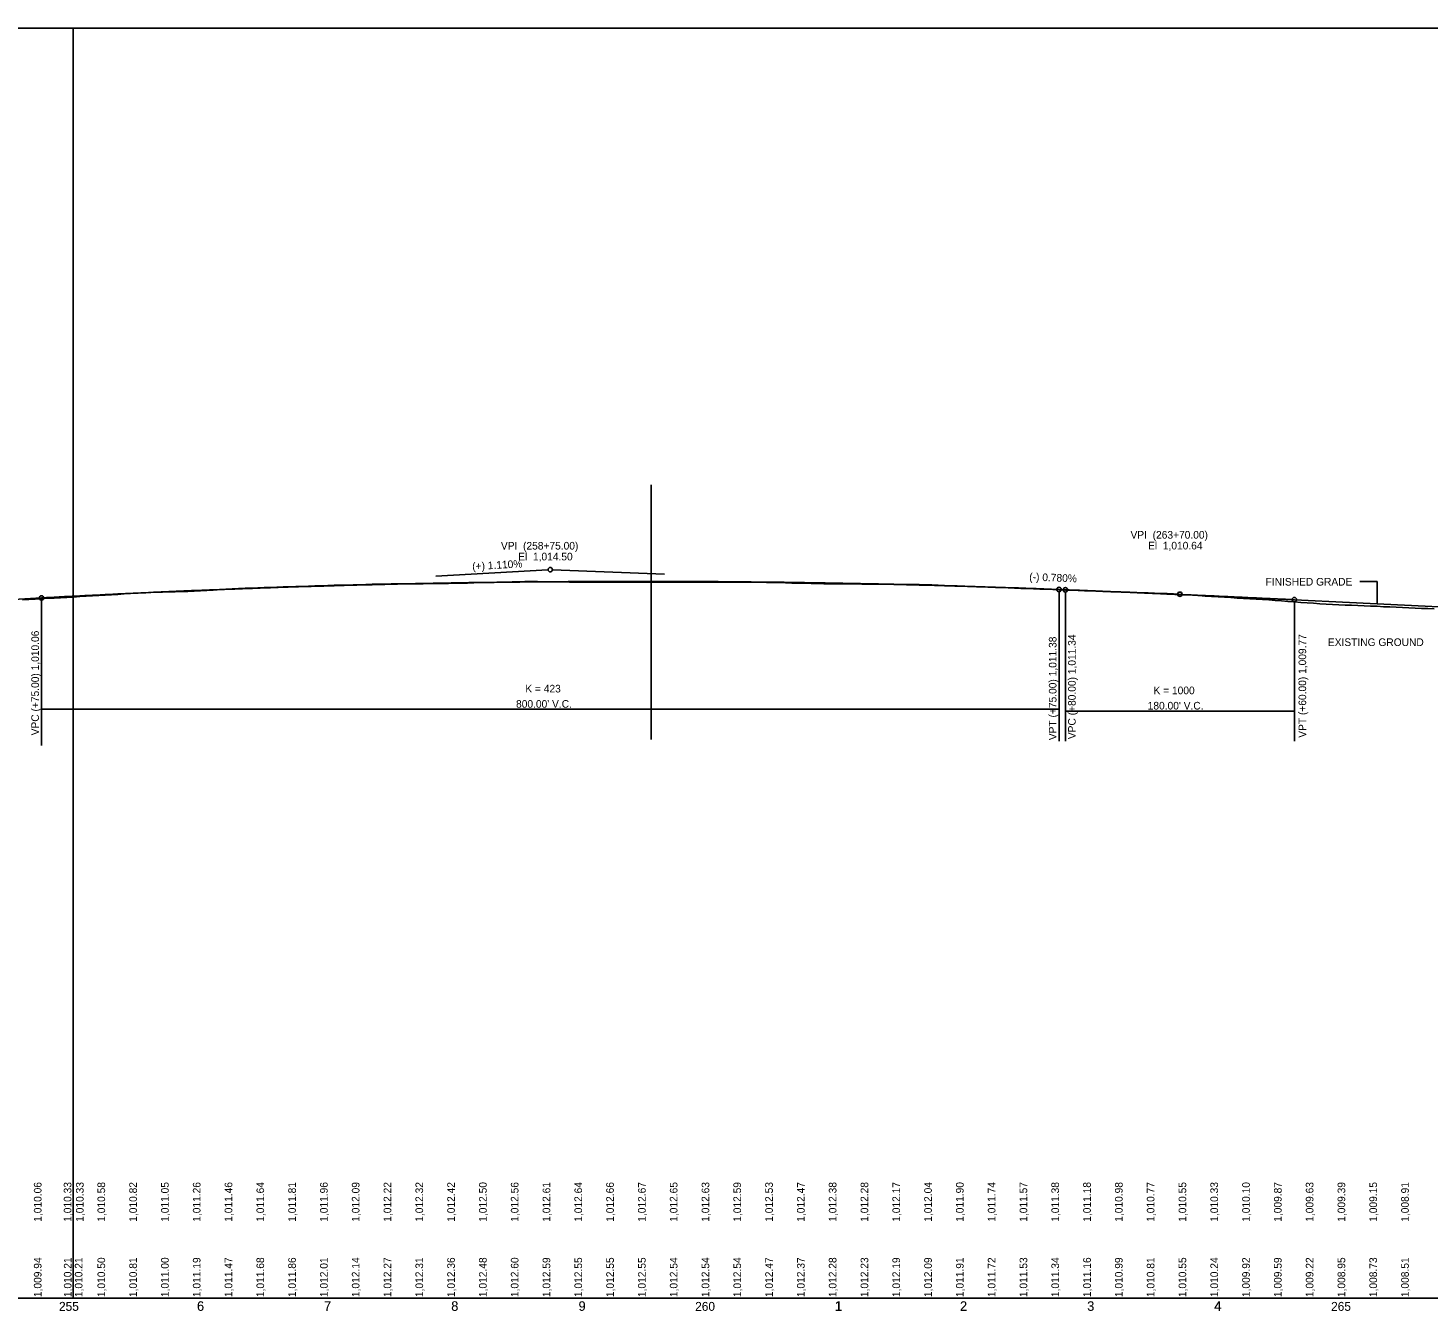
# Model space of a CAD drawing. Extents: x 1608361 to 16979326, y 1092015 to 12565288.
# Drawn here: x 16974450 to 16975551, y 12564278 to 12565286 of the extents above; entities that cross this region are included whole.
import ezdxf

# ---------------------------------------------------------------- set-up
doc = ezdxf.new("R2010")
doc.units = 0
for name, color, linetype in [('CLS_Median', 7, 'Continuous'), ('Default', 7, 'Continuous'), ('points EP', 7, 'Continuous'), ('RD_DDB_EX_Tx', 7, 'Continuous'), ('RD_EX_Fence_ChLk', 7, 'Continuous'), ('RD_EX_H2O', 7, 'Continuous'), ('RD_EX_RW_Approx', 7, 'Continuous'), ('RD_EX_SU_Water', 7, 'Continuous'), ('RD_EX_UT', 7, 'Continuous'), ('RD_HC_TX_Rel_Sta50', 7, 'Continuous'), ('RD_PD_BCA', 7, 'Continuous'), ('RD_PD_Final_TX', 7, 'Continuous'), ('TEXT2', 7, 'Continuous')]:
    doc.layers.add(name, color=color, linetype=linetype)

msp = doc.modelspace()

# ---------------------------------------------------------------- linework, layer by layer
at = {"layer": 'CLS_Median'}
for p, q in [((16975497.2, 12564851), (16975510.6, 12564851)), ((16975510.6, 12564851), (16975510.6, 12564833.5))]:
    msp.add_line(p, q, dxfattribs=at)
at = {"layer": 'Default'}
for points in [[(16972985.6, 12564287.8), (16974485.6, 12564287.8), (16974485.6, 12565286), (16972985.6, 12565286)], [(16974485.6, 12564287.8), (16975985.6, 12564287.8), (16975985.6, 12565286), (16974485.6, 12565286)]]:
    msp.add_lwpolyline(points, close=True, dxfattribs=at)
at = {"layer": 'RD_EX_Fence_ChLk'}
for p, q in [((16975260.6, 12564725.4), (16975260.6, 12564842.9)), ((16975265.6, 12564725.4), (16975265.6, 12564842.7)), ((16974460.6, 12564722.2), (16974460.6, 12564836.3)), ((16975445.6, 12564725.4), (16975445.6, 12564834.9)), ((16974460.6, 12564750.6), (16975260.6, 12564750.6)), ((16975265.6, 12564749.2), (16975445.6, 12564749.2))]:
    msp.add_line(p, q, dxfattribs=at)
for centre in [(16974460.6, 12564838.1), (16975260.6, 12564844.7), (16975265.6, 12564844.5), (16975445.6, 12564836.7)]:
    msp.add_circle(centre, 1.75, dxfattribs=at)
at = {"layer": 'RD_EX_H2O'}
for points in [[(16974485.6, 12564838.8), (16974490.6, 12564839.1), (16974495.6, 12564839.4), (16974500.6, 12564839.7), (16974505.6, 12564840), (16974510.6, 12564840.3), (16974515.6, 12564840.6), (16974520.6, 12564840.9), (16974525.6, 12564841.2), (16974530.6, 12564841.5), (16974535.6, 12564841.8), (16974540.6, 12564842.2), (16974545.6, 12564842.3), (16974550.6, 12564842.5), (16974555.6, 12564842.6), (16974560.6, 12564842.8), (16974565.6, 12564842.9), (16974570.6, 12564843.1), (16974575.6, 12564843.2), (16974580.6, 12564843.5), (16974585.6, 12564843.7), (16974590.6, 12564844), (16974595.6, 12564844.3), (16974600.6, 12564844.6), (16974605.6, 12564844.9), (16974610.6, 12564845.2), (16974615.6, 12564845.4), (16974620.6, 12564845.7), (16974625.6, 12564845.8), (16974630.6, 12564846), (16974635.6, 12564846.2), (16974640.6, 12564846.4), (16974645.6, 12564846.6), (16974650.6, 12564846.7), (16974655.6, 12564846.9), (16974660.6, 12564847.1), (16974665.6, 12564847.2), (16974670.6, 12564847.4), (16974675.6, 12564847.5), (16974680.6, 12564847.7), (16974685.6, 12564847.8), (16974690.6, 12564848), (16974695.6, 12564848.1), (16974700.6, 12564848.2), (16974705.6, 12564848.4), (16974710.6, 12564848.5), (16974715.6, 12564848.6), (16974720.6, 12564848.8), (16974725.6, 12564848.9), (16974730.6, 12564849), (16974735.6, 12564849.1), (16974740.6, 12564849.2), (16974745.6, 12564849.3), (16974750.6, 12564849.3), (16974755.6, 12564849.3), (16974760.6, 12564849.3), (16974765.6, 12564849.4), (16974770.6, 12564849.4), (16974775.6, 12564849.4), (16974780.6, 12564849.5), (16974785.6, 12564849.6), (16974790.6, 12564849.7), (16974795.6, 12564849.8), (16974800.6, 12564849.9), (16974805.6, 12564850.1), (16974810.6, 12564850.2), (16974815.6, 12564850.3), (16974820.6, 12564850.4), (16974825.6, 12564850.5), (16974830.6, 12564850.7), (16974835.6, 12564850.8), (16974840.6, 12564850.9), (16974845.6, 12564850.9), (16974850.6, 12564850.9), (16974855.6, 12564850.8), (16974860.6, 12564850.8), (16974865.6, 12564850.7), (16974870.6, 12564850.7), (16974875.6, 12564850.6), (16974880.6, 12564850.6), (16974885.6, 12564850.5), (16974890.6, 12564850.5), (16974895.6, 12564850.5), (16974900.6, 12564850.5), (16974905.6, 12564850.5), (16974910.6, 12564850.5), (16974915.6, 12564850.5), (16974920.6, 12564850.5), (16974925.6, 12564850.5), (16974930.6, 12564850.5), (16974935.6, 12564850.5), (16974940.6, 12564850.5), (16974945.6, 12564850.5), (16974950.6, 12564850.5), (16974955.6, 12564850.5), (16974960.6, 12564850.5), (16974965.6, 12564850.5), (16974970.6, 12564850.5), (16974975.6, 12564850.5), (16974980.6, 12564850.5), (16974985.6, 12564850.5)], [(16974985.6, 12564850.5), (16974990.6, 12564850.5), (16974995.6, 12564850.5), (16975000.6, 12564850.5), (16975005.6, 12564850.5), (16975010.6, 12564850.5), (16975015.6, 12564850.5), (16975020.6, 12564850.5), (16975025.6, 12564850.4), (16975030.6, 12564850.3), (16975035.6, 12564850.2), (16975040.6, 12564850.1), (16975045.6, 12564849.9), (16975050.6, 12564849.8), (16975055.6, 12564849.7), (16975060.6, 12564849.6), (16975065.6, 12564849.5), (16975070.6, 12564849.4), (16975075.6, 12564849.3), (16975080.6, 12564849.2), (16975085.6, 12564849.2), (16975090.6, 12564849.1), (16975095.6, 12564849.1), (16975100.6, 12564849.1), (16975105.6, 12564849), (16975110.6, 12564849), (16975115.6, 12564848.9), (16975120.6, 12564848.9), (16975125.6, 12564848.8), (16975130.6, 12564848.8), (16975135.6, 12564848.7), (16975140.6, 12564848.7), (16975145.6, 12564848.6), (16975150.6, 12564848.6), (16975155.6, 12564848.4), (16975160.6, 12564848.3), (16975165.6, 12564848.1), (16975170.6, 12564847.9), (16975175.6, 12564847.7), (16975180.6, 12564847.5), (16975185.6, 12564847.3), (16975190.6, 12564847.1), (16975195.6, 12564846.9), (16975200.6, 12564846.8), (16975205.6, 12564846.6), (16975210.6, 12564846.4), (16975215.6, 12564846.2), (16975220.6, 12564846), (16975225.6, 12564845.8), (16975230.6, 12564845.6), (16975235.6, 12564845.4), (16975240.6, 12564845.3), (16975245.6, 12564845.1), (16975250.6, 12564844.9), (16975255.6, 12564844.7), (16975260.6, 12564844.5), (16975265.6, 12564844.3), (16975270.6, 12564844.1), (16975275.6, 12564844), (16975280.6, 12564843.8), (16975285.6, 12564843.6), (16975290.6, 12564843.4), (16975295.6, 12564843.2), (16975300.6, 12564843.1), (16975305.6, 12564842.9), (16975310.6, 12564842.7), (16975315.6, 12564842.5), (16975320.6, 12564842.4), (16975325.6, 12564842.2), (16975330.6, 12564842), (16975335.6, 12564841.8), (16975340.6, 12564841.6), (16975345.6, 12564841.5), (16975350.6, 12564841.2), (16975355.6, 12564840.9), (16975360.6, 12564840.6), (16975365.6, 12564840.2), (16975370.6, 12564839.9), (16975375.6, 12564839.6), (16975380.6, 12564839.3), (16975385.6, 12564839), (16975390.6, 12564838.7), (16975395.6, 12564838.4), (16975400.6, 12564838), (16975405.6, 12564837.7), (16975410.6, 12564837.4), (16975415.6, 12564837.1), (16975420.6, 12564836.8), (16975425.6, 12564836.5), (16975430.6, 12564836.1), (16975435.6, 12564835.7), (16975440.6, 12564835.3), (16975445.6, 12564835), (16975450.6, 12564834.6), (16975455.6, 12564834.2), (16975460.6, 12564833.9), (16975465.6, 12564833.5), (16975470.6, 12564833.1), (16975475.6, 12564832.9), (16975480.6, 12564832.7), (16975485.6, 12564832.5)], [(16974445.6, 12564836.7), (16974450.6, 12564836.9), (16974455.6, 12564837.2), (16974460.6, 12564837.5), (16974465.6, 12564837.8), (16974470.6, 12564838), (16974475.6, 12564838.3), (16974480.6, 12564838.5), (16974485.6, 12564838.8)], [(16975485.6, 12564832.5), (16975490.6, 12564832.3), (16975495.6, 12564832.1), (16975500.6, 12564831.9), (16975505.6, 12564831.7), (16975510.6, 12564831.5), (16975515.6, 12564831.2), (16975520.6, 12564831), (16975525.6, 12564830.8), (16975530.6, 12564830.6), (16975535.6, 12564830.3), (16975540.6, 12564830.1), (16975545.6, 12564829.9), (16975550.6, 12564829.7), (16975555.6, 12564829.6)]]:
    msp.add_lwpolyline(points, dxfattribs=at)
at = {"layer": 'RD_EX_RW_Approx'}
for p, q in [((16974770.7, 12564855.3), (16974858.8, 12564860.2)), ((16974950.5, 12564856.8), (16974862.3, 12564860.2)), ((16975265.6, 12564844.5), (16975353.8, 12564841)), ((16975445.5, 12564836.7), (16975357.3, 12564840.9))]:
    msp.add_line(p, q, dxfattribs=at)
for centre in [(16974860.6, 12564860.3), (16975355.6, 12564841)]:
    msp.add_circle(centre, 1.75, dxfattribs=at)
at = {"layer": 'RD_EX_UT'}
msp.add_line((16972985.6, 12564287.8), (16978789.9, 12564287.8), dxfattribs=at)
at = {"layer": 'RD_HC_TX_Rel_Sta50'}
for p, q in [((16975260.6, 12564844.7), (16975265.6, 12564844.5)), ((16974390.6, 12564834.2), (16974460.6, 12564838.1)), ((16975445.6, 12564836.7), (16975735.6, 12564822.7))]:
    msp.add_line(p, q, dxfattribs=at)
for points in [[(16974460.6, 12564838.1), (16974476.6, 12564839), (16974492.6, 12564839.8), (16974508.6, 12564840.6), (16974524.6, 12564841.4), (16974540.6, 12564842.1), (16974556.6, 12564842.9), (16974572.6, 12564843.6), (16974588.6, 12564844.2), (16974604.6, 12564844.8), (16974620.6, 12564845.4), (16974636.6, 12564846), (16974652.6, 12564846.6), (16974668.6, 12564847.1), (16974684.6, 12564847.5), (16974700.6, 12564848), (16974716.6, 12564848.4), (16974732.6, 12564848.8), (16974748.6, 12564849.2), (16974764.6, 12564849.5), (16974780.6, 12564849.8), (16974796.6, 12564850.1), (16974812.6, 12564850.3), (16974828.6, 12564850.5), (16974844.6, 12564850.7), (16974860.6, 12564850.8), (16974876.6, 12564850.9), (16974892.6, 12564851), (16974908.6, 12564851.1), (16974924.6, 12564851.1), (16974940.6, 12564851.1), (16974956.6, 12564851.1), (16974972.6, 12564851), (16974988.6, 12564850.9), (16975004.6, 12564850.8), (16975020.6, 12564850.6), (16975036.6, 12564850.5), (16975052.6, 12564850.2), (16975068.6, 12564850), (16975084.6, 12564849.7), (16975100.6, 12564849.4), (16975116.6, 12564849.1), (16975132.6, 12564848.7), (16975148.6, 12564848.3), (16975164.6, 12564847.9), (16975180.6, 12564847.4), (16975196.6, 12564846.9), (16975212.6, 12564846.4), (16975228.6, 12564845.9), (16975244.6, 12564845.3), (16975260.6, 12564844.7)], [(16975265.6, 12564844.5), (16975269.2, 12564844.3), (16975272.8, 12564844.2), (16975276.4, 12564844.1), (16975280, 12564843.9), (16975283.6, 12564843.8), (16975287.2, 12564843.6), (16975290.8, 12564843.5), (16975294.4, 12564843.3), (16975298, 12564843.2), (16975301.6, 12564843), (16975305.2, 12564842.9), (16975308.8, 12564842.8), (16975312.4, 12564842.6), (16975316, 12564842.5), (16975319.6, 12564842.3), (16975323.2, 12564842.2), (16975326.8, 12564842), (16975330.4, 12564841.9), (16975334, 12564841.7), (16975337.6, 12564841.5), (16975341.2, 12564841.4), (16975344.8, 12564841.2), (16975348.4, 12564841.1), (16975352, 12564840.9), (16975355.6, 12564840.8), (16975359.2, 12564840.6), (16975362.8, 12564840.5), (16975366.4, 12564840.3), (16975370, 12564840.1), (16975373.6, 12564840), (16975377.2, 12564839.8), (16975380.8, 12564839.7), (16975384.4, 12564839.5), (16975388, 12564839.3), (16975391.6, 12564839.2), (16975395.2, 12564839), (16975398.8, 12564838.8), (16975402.4, 12564838.7), (16975406, 12564838.5), (16975409.6, 12564838.3), (16975413.2, 12564838.2), (16975416.8, 12564838), (16975420.4, 12564837.8), (16975424, 12564837.7), (16975427.6, 12564837.5), (16975431.2, 12564837.3), (16975434.8, 12564837.2), (16975438.4, 12564837), (16975442, 12564836.8), (16975445.6, 12564836.7)]]:
    msp.add_spline(points, degree=3, dxfattribs=at)
at = {"layer": 'RD_PD_BCA'}
msp.add_line((16974940, 12564726.8), (16974940, 12564926.9), dxfattribs=at)

# ---------------------------------------------------------------- texts
at = {"layer": 'CLS_Median'}
msp.add_text('FINISHED GRADE', height=6, dxfattribs=at).set_placement((16975423, 12564847.8))
at = {"layer": 'points EP'}
for s, rotation, p in [('(+) 1.110%', 3.1767, (16974799.4, 12564859.9)), ('(-) 0.780%', 357.7666, (16975237.1, 12564851.8))]:
    msp.add_text(s, height=6, rotation=rotation, dxfattribs=at).set_placement(p)
at = {"layer": 'RD_DDB_EX_Tx'}
msp.add_text('EXISTING GROUND', height=6, dxfattribs=at).set_placement((16975472, 12564800.3))
at = {"layer": 'RD_EX_Fence_ChLk'}
for s, p in [('VPC (+75.00) 1,010.06', (16974458.6, 12564730.1)), ('VPT (+75.00) 1,011.38', (16975258.6, 12564726.3)), ('VPC (+80.00) 1,011.34', (16975273.7, 12564727.1)), ('VPT (+60.00) 1,009.77', (16975454.9, 12564728.2))]:
    msp.add_text(s, height=6, rotation=90, dxfattribs=at).set_placement(p)
for s, p in [('K = 423', (16974841, 12564763.8)), ('K = 1000', (16975334.9, 12564762.4)), ("800.00' V.C.", (16974833.7, 12564751.8)), ("180.00' V.C.", (16975330.3, 12564750.4))]:
    msp.add_text(s, height=6, dxfattribs=at).set_placement(p)
at = {"layer": 'RD_EX_RW_Approx'}
for s, p in [('VPI  (258+75.00)', (16974821.8, 12564876.1)), ('VPI  (263+70.00)', (16975316.8, 12564884.7)), ('El  1,010.64', (16975330.6, 12564876.2)), ('El  1,014.50', (16974835.4, 12564867.6))]:
    msp.add_text(s, height=6, dxfattribs=at).set_placement(p)
at = {"layer": 'RD_EX_SU_Water'}
for s, p in [('1,010.06', (16974460.6, 12564347.8)), ('1,010.33', (16974484.1, 12564347.8)), ('1,010.33', (16974493.7, 12564347.8)), ('1,010.58', (16974510.6, 12564347.8)), ('1,010.82', (16974535.6, 12564347.8)), ('1,011.05', (16974560.6, 12564347.8)), ('1,011.26', (16974585.6, 12564347.8)), ('1,011.46', (16974610.6, 12564347.8)), ('1,011.64', (16974635.6, 12564347.8)), ('1,011.81', (16974660.6, 12564347.8)), ('1,011.96', (16974685.6, 12564347.8)), ('1,012.09', (16974710.6, 12564347.8)), ('1,012.22', (16974735.6, 12564347.8)), ('1,012.32', (16974760.6, 12564347.8)), ('1,012.42', (16974785.6, 12564347.8)), ('1,012.50', (16974810.6, 12564347.8)), ('1,012.56', (16974835.6, 12564347.8)), ('1,012.61', (16974860.6, 12564347.8)), ('1,012.64', (16974885.6, 12564347.8)), ('1,012.66', (16974910.6, 12564347.8)), ('1,012.67', (16974935.6, 12564347.8)), ('1,012.65', (16974960.6, 12564347.8)), ('1,012.63', (16974985.6, 12564347.8)), ('1,012.59', (16975010.6, 12564347.8)), ('1,012.53', (16975035.6, 12564347.8)), ('1,012.47', (16975060.6, 12564347.8)), ('1,012.38', (16975085.6, 12564347.8)), ('1,012.28', (16975110.6, 12564347.8)), ('1,012.17', (16975135.6, 12564347.8)), ('1,012.04', (16975160.6, 12564347.8)), ('1,011.90', (16975185.6, 12564347.8)), ('1,011.74', (16975210.6, 12564347.8)), ('1,011.57', (16975235.6, 12564347.8)), ('1,011.38', (16975260.6, 12564347.8)), ('1,011.18', (16975285.6, 12564347.8)), ('1,010.98', (16975310.6, 12564347.8)), ('1,010.77', (16975335.6, 12564347.8)), ('1,010.55', (16975360.6, 12564347.8)), ('1,010.33', (16975385.6, 12564347.8)), ('1,010.10', (16975410.6, 12564347.8)), ('1,009.87', (16975435.6, 12564347.8)), ('1,009.63', (16975460.6, 12564347.8)), ('1,009.39', (16975485.6, 12564347.8)), ('1,009.15', (16975510.6, 12564347.8)), ('1,008.91', (16975535.6, 12564347.8))]:
    msp.add_text(s, height=6, rotation=90, dxfattribs=at).set_placement(p)
at = {"layer": 'RD_PD_Final_TX'}
for s, height, p in [('255', 7, (16974474.3, 12564277.8)), ('255', 7, (16974474.4, 12564277.8)), ('6', 7.5, (16974582.8, 12564277.8)), ('6', 7.5, (16974582.9, 12564277.8)), ('7', 7.5, (16974682.7, 12564277.8)), ('7', 7.5, (16974682.8, 12564277.8)), ('8', 7.5, (16974782.7, 12564277.8)), ('8', 7.5, (16974782.8, 12564277.8)), ('9', 7.5, (16974882.8, 12564277.8)), ('9', 7.5, (16974882.9, 12564277.8)), ('260', 7, (16974974.5, 12564277.8)), ('260', 7, (16974974.5, 12564277.8)), ('1', 7.5, (16975084.2, 12564277.8)), ('1', 7.5, (16975084.6, 12564277.8)), ('2', 7.5, (16975182.7, 12564277.8)), ('2', 7.5, (16975182.8, 12564277.8)), ('3', 7.5, (16975282.7, 12564277.8)), ('3', 7.5, (16975282.8, 12564277.8)), ('4', 7.5, (16975382.5, 12564277.8)), ('4', 7.5, (16975382.8, 12564277.8)), ('265', 7, (16975474.5, 12564277.8)), ('265', 7, (16975474.5, 12564277.8))]:
    msp.add_text(s, height=height, dxfattribs=at).set_placement(p)
at = {"layer": 'TEXT2'}
for s, p in [('1,009.94', (16974460.6, 12564288.6)), ('1,010.21', (16974484.2, 12564288.6)), ('1,010.21', (16974492.8, 12564288.6)), ('1,010.50', (16974510.6, 12564288.6)), ('1,010.81', (16974535.6, 12564288.6)), ('1,011.00', (16974560.6, 12564288.6)), ('1,011.19', (16974585.6, 12564288.6)), ('1,011.47', (16974610.6, 12564288.6)), ('1,011.68', (16974635.6, 12564288.6)), ('1,011.86', (16974660.6, 12564288.6)), ('1,012.01', (16974685.6, 12564288.6)), ('1,012.14', (16974710.6, 12564288.6)), ('1,012.27', (16974735.6, 12564288.6)), ('1,012.31', (16974760.6, 12564288.6)), ('1,012.36', (16974785.6, 12564288.6)), ('1,012.48', (16974810.6, 12564288.6)), ('1,012.60', (16974835.6, 12564288.6)), ('1,012.59', (16974860.6, 12564288.6)), ('1,012.55', (16974885.6, 12564288.6)), ('1,012.55', (16974910.6, 12564288.6)), ('1,012.55', (16974935.6, 12564288.6)), ('1,012.54', (16974960.6, 12564288.6)), ('1,012.54', (16974985.6, 12564288.6)), ('1,012.54', (16975010.6, 12564288.6)), ('1,012.47', (16975035.6, 12564288.6)), ('1,012.37', (16975060.6, 12564288.6)), ('1,012.28', (16975085.6, 12564288.6)), ('1,012.23', (16975110.6, 12564288.6)), ('1,012.19', (16975135.6, 12564288.6)), ('1,012.09', (16975160.6, 12564288.6)), ('1,011.91', (16975185.6, 12564288.6)), ('1,011.72', (16975210.6, 12564288.6)), ('1,011.53', (16975235.6, 12564288.6)), ('1,011.34', (16975260.6, 12564288.6)), ('1,011.16', (16975285.6, 12564288.6)), ('1,010.99', (16975310.6, 12564288.6)), ('1,010.81', (16975335.6, 12564288.6)), ('1,010.55', (16975360.6, 12564288.6)), ('1,010.24', (16975385.6, 12564288.6)), ('1,009.92', (16975410.6, 12564288.6)), ('1,009.59', (16975435.6, 12564288.6)), ('1,009.22', (16975460.6, 12564288.6)), ('1,008.95', (16975485.6, 12564288.6)), ('1,008.73', (16975510.6, 12564288.6)), ('1,008.51', (16975535.6, 12564288.6))]:
    msp.add_text(s, height=6, rotation=90, dxfattribs=at).set_placement(p)

doc.saveas('drawing.dxf')
